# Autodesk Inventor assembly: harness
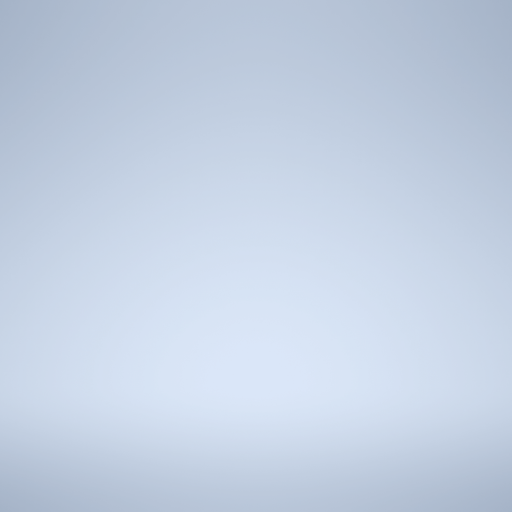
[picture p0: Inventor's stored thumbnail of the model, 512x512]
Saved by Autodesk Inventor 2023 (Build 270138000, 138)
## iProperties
Part Number: harness
Document SubType Name: Assembly
Created: 2002-07
HarnessSettings: <HarnessSettings><Defaults><Segments><Diameter value="0.200 in" fromwires="True"/><Offset value="0.100 in"/><ColorStyle value="Blue"/><BendRadius value="19" fro
Control State: 0
Master: False
Checked Out: False
Shininess: 64.0
Length Units: 11272
Angle Units: 11279
Time Units: 11290
Mass Units: 11286
Length Display Precision: 3
Angle Display Precision: 2
Compacted: True
Density: 0.0
Volumn: 0.0
Area: 0.0
PropertySet Name: Model Information
HarnessSettings: <HarnessSettings><Defaults><Segments><Diameter value="0.200 in" fromwires="True"/><Offset value="0.100 in"/><ColorStyle value="Niebieska — farba ścienna — lśnią
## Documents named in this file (1)
- C:\Users\ENU\Desktop\plk\2\harness.iam
